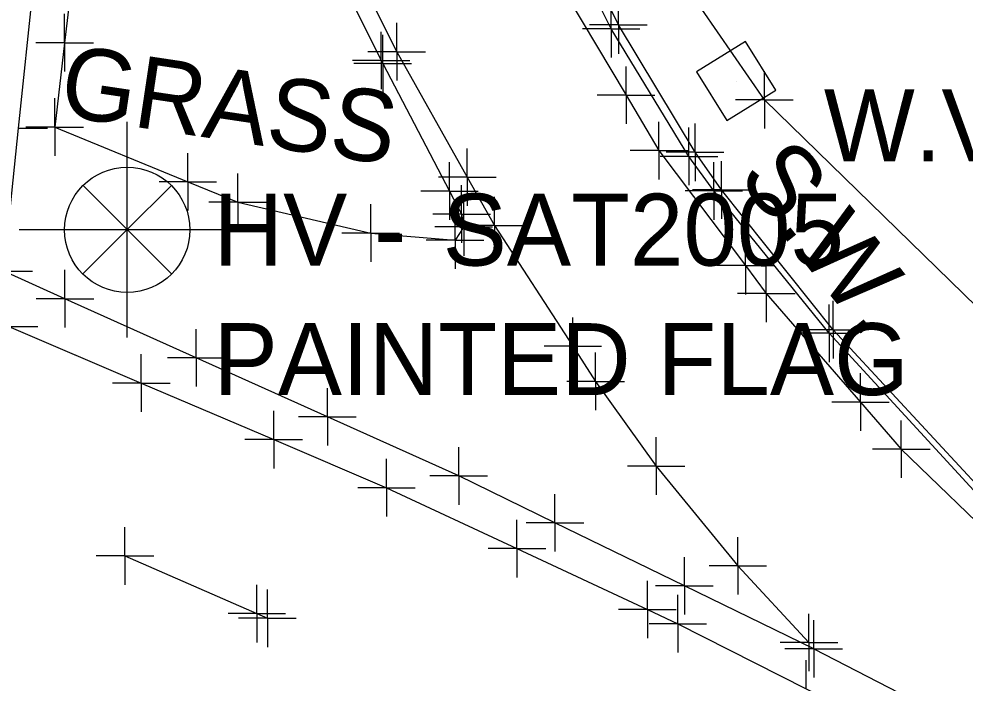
# Model space of a CAD drawing. Extents: x 0 to 1944463, y 0 to 420651.
# Drawn here: x 1942744.5 to 1942810.2, y 417858.9 to 417905.1 of the extents above; entities that cross this region are included whole.
import ezdxf

# ---------------------------------------------------------------- set-up
doc = ezdxf.new("R2010")
doc.units = 0
for name, color, linetype in [('AERIAL - CTRL - Points', 7, 'Continuous'), ('AERIAL - CTRL - Text', 7, 'Continuous'), ('SUR - DTM - Breaklines', 7, 'Continuous'), ('SUR - DTM - Breaklines - Points - Locators', 7, 'Continuous'), ('SUR - TR-CTRL - Pavement Marking', 7, 'Continuous'), ('SUR - TR-CTRL - Pavement Marking - Points - Locators', 7, 'Continuous'), ('SUR - TRAN - Features', 7, 'Continuous'), ('SUR - TRAN - Features - Points - Locators', 7, 'Continuous'), ('SUR - TRAN - Features Text', 7, 'Continuous'), ('SUR - UTL - Water', 7, 'Continuous'), ('SUR - UTL - Water Text', 7, 'Continuous'), ('SUR - VEG - Features Text', 7, 'Continuous')]:
    doc.layers.add(name, color=color, linetype=linetype)

msp = doc.modelspace()

# ---------------------------------------------------------------- linework, layer by layer
at = {"layer": 'AERIAL - CTRL - Points'}
for p, q in [((1942752.036, 417890.416), (1942752.036, 417897.916)), ((1942752.036, 417890.416), (1942748.967, 417893.485)), ((1942752.036, 417890.416), (1942755.104, 417893.485)), ((1942744.536, 417890.416), (1942752.036, 417890.416)), ((1942748.952, 417887.333), (1942752.036, 417890.416)), ((1942752.036, 417890.416), (1942752.036, 417890.416)), ((1942752.036, 417890.416), (1942759.536, 417890.416)), ((1942755.119, 417887.333), (1942752.036, 417890.416)), ((1942752.036, 417882.917), (1942752.036, 417890.416))]:
    msp.add_line(p, q, dxfattribs=at)
msp.add_circle((1942752.036, 417890.401), 4.35, dxfattribs=at)
at = {"layer": 'SUR - DTM - Breaklines'}
msp.add_lwpolyline([(1942845.653, 417851.435), (1942844.565, 417850.194), (1942842.765, 417849.553), (1942840.798, 417849.919), (1942830.793, 417855.545), (1942821.429, 417862.859), (1942815.227, 417868.426), (1942812.749, 417870.855), (1942801.064, 417883.457), (1942793.306, 417893.178), (1942791.482, 417895.793), (1942786.152, 417904.647), (1942777.316, 417922.399), (1942769.183, 417947.203), (1942767.419, 417957.597), (1942765.99, 417970.655), (1942765.855, 417974.495), (1942767.539, 418005.277), (1942768.104, 418011.353)], dxfattribs=at)
at = {"layer": 'SUR - DTM - Breaklines - Points - Locators'}
for p, q in [((1942786.152, 417904.647), (1942786.152, 417906.647)), ((1942786.152, 417904.647), (1942784.152, 417904.647)), ((1942786.152, 417904.647), (1942788.152, 417904.647)), ((1942786.152, 417904.647), (1942786.152, 417902.647)), ((1942791.482, 417895.793), (1942791.482, 417897.793)), ((1942791.482, 417895.793), (1942789.482, 417895.793)), ((1942791.482, 417895.793), (1942793.482, 417895.793)), ((1942791.482, 417895.793), (1942791.482, 417893.793)), ((1942793.306, 417893.178), (1942793.306, 417895.178)), ((1942793.306, 417893.178), (1942791.306, 417893.178)), ((1942793.306, 417893.178), (1942795.306, 417893.178)), ((1942793.306, 417893.178), (1942793.306, 417891.178)), ((1942801.064, 417883.457), (1942801.064, 417885.457)), ((1942801.064, 417883.457), (1942799.064, 417883.457)), ((1942801.064, 417883.457), (1942803.064, 417883.457)), ((1942801.064, 417883.457), (1942801.064, 417881.457))]:
    msp.add_line(p, q, dxfattribs=at)
at = {"layer": 'SUR - TR-CTRL - Pavement Marking'}
for points in [[(1942756.253, 418008.604), (1942756.832, 417999.459), (1942757.925, 417989.519), (1942758.231, 417986.732), (1942760.046, 417976.898), (1942760.467, 417974.617), (1942762.281, 417964.783), (1942762.952, 417961.148), (1942765.097, 417952.301), (1942767.192, 417944.847), (1942770.176, 417935.303), (1942770.256, 417935.048), (1942772.517, 417928.408), (1942775.859, 417919.929), (1942780.296, 417910.968), (1942781.583, 417908.367), (1942786.685, 417899.767), (1942788.971, 417895.911), (1942794.975, 417887.914), (1942796.42, 417885.987), (1942802.968, 417878.429), (1942805.803, 417875.157), (1942813, 417868.214)], [(1942799.725, 417861.277), (1942790.736, 417865.658), (1942781.747, 417870.039), (1942775.062, 417873.297), (1942765.944, 417877.403), (1942756.825, 417881.508), (1942747.707, 417885.614), (1942743.465, 417887.524), (1942744.493, 417897.471), (1942745.521, 417907.418), (1942746.549, 417917.365), (1942747.578, 417927.312), (1942748.606, 417937.259), (1942749.634, 417947.206), (1942750.63, 417956.84)], [(1942752.579, 417949.819), (1942754.255, 417944.892), (1942756.21, 417938.529), (1942758.752, 417930.8), (1942761.496, 417923.192), (1942763.64, 417917.67), (1942766.697, 417910.933), (1942770.76, 417902.785), (1942775.654, 417894.064), (1942777.544, 417890.697), (1942782.986, 417882.308), (1942784.568, 417879.87), (1942788.778, 417873.987), (1942794.451, 417867.048), (1942799.385, 417861.72)], [(1942743.821, 417883.68), (1942753.017, 417879.751), (1942762.213, 417875.823), (1942770.046, 417872.476), (1942779.106, 417868.245), (1942788.166, 417864.013), (1942790.281, 417863.025), (1942799.195, 417858.492), (1942808.108, 417853.959), (1942814.469, 417850.724), (1942823.271, 417845.977), (1942832.073, 417841.23), (1942837.137, 417838.5), (1942845.787, 417833.481), (1942854.436, 417828.462), (1942863.086, 417823.444), (1942865.149, 417822.246), (1942873.606, 417816.91), (1942882.063, 417811.573), (1942888.586, 417807.457), (1942896.946, 417801.969)], [(1942751.882, 417867.738), (1942761.042, 417863.726), (1942761.775, 417863.405)]]:
    msp.add_lwpolyline(points, dxfattribs=at)
at = {"layer": 'SUR - TR-CTRL - Pavement Marking - Points - Locators'}
for p, q in [((1942770.76, 417902.785), (1942770.76, 417904.785)), ((1942770.76, 417902.785), (1942768.76, 417902.785)), ((1942770.76, 417902.785), (1942772.76, 417902.785)), ((1942770.76, 417902.785), (1942770.76, 417900.785)), ((1942786.685, 417899.767), (1942786.685, 417901.767)), ((1942786.685, 417899.767), (1942784.685, 417899.767)), ((1942786.685, 417899.767), (1942788.685, 417899.767)), ((1942786.685, 417899.767), (1942786.685, 417897.767)), ((1942744.493, 417897.471), (1942746.493, 417897.471)), ((1942788.971, 417895.911), (1942788.971, 417897.911)), ((1942775.654, 417894.064), (1942775.654, 417896.064)), ((1942788.971, 417895.911), (1942786.971, 417895.911)), ((1942788.971, 417895.911), (1942790.971, 417895.911)), ((1942788.971, 417895.911), (1942788.971, 417893.911)), ((1942775.654, 417894.064), (1942773.654, 417894.064)), ((1942775.654, 417894.064), (1942777.654, 417894.064)), ((1942775.654, 417894.064), (1942775.654, 417892.064)), ((1942777.544, 417890.697), (1942777.544, 417892.697)), ((1942777.544, 417890.697), (1942775.544, 417890.697)), ((1942777.544, 417890.697), (1942779.544, 417890.697)), ((1942777.544, 417890.697), (1942777.544, 417888.697)), ((1942794.975, 417887.914), (1942794.975, 417889.914)), ((1942743.465, 417887.524), (1942745.465, 417887.524)), ((1942747.707, 417885.614), (1942747.707, 417887.614)), ((1942794.975, 417887.914), (1942792.975, 417887.914)), ((1942794.975, 417887.914), (1942796.975, 417887.914)), ((1942794.975, 417887.914), (1942794.975, 417885.914)), ((1942796.42, 417885.987), (1942796.42, 417887.987)), ((1942747.707, 417885.614), (1942745.707, 417885.614)), ((1942747.707, 417885.614), (1942749.707, 417885.614)), ((1942747.707, 417885.614), (1942747.707, 417883.614)), ((1942796.42, 417885.987), (1942794.42, 417885.987)), ((1942796.42, 417885.987), (1942798.42, 417885.987)), ((1942796.42, 417885.987), (1942796.42, 417883.987)), ((1942782.986, 417882.308), (1942782.986, 417884.308)), ((1942743.821, 417883.68), (1942745.821, 417883.68)), ((1942756.825, 417881.508), (1942756.825, 417883.508)), ((1942782.986, 417882.308), (1942780.986, 417882.308)), ((1942782.986, 417882.308), (1942784.986, 417882.308)), ((1942782.986, 417882.308), (1942782.986, 417880.308)), ((1942753.017, 417879.751), (1942753.017, 417881.751)), ((1942784.568, 417879.87), (1942784.568, 417881.87)), ((1942756.825, 417881.508), (1942754.825, 417881.508)), ((1942756.825, 417881.508), (1942758.825, 417881.508)), ((1942756.825, 417881.508), (1942756.825, 417879.508)), ((1942802.968, 417878.429), (1942802.968, 417880.429)), ((1942753.017, 417879.751), (1942751.017, 417879.751)), ((1942753.017, 417879.751), (1942755.017, 417879.751)), ((1942753.017, 417879.751), (1942753.017, 417877.751)), ((1942784.568, 417879.87), (1942782.568, 417879.87)), ((1942784.568, 417879.87), (1942786.568, 417879.87)), ((1942784.568, 417879.87), (1942784.568, 417877.87)), ((1942765.944, 417877.403), (1942765.944, 417879.403)), ((1942802.968, 417878.429), (1942800.968, 417878.429)), ((1942802.968, 417878.429), (1942804.968, 417878.429)), ((1942802.968, 417878.429), (1942802.968, 417876.429)), ((1942762.213, 417875.823), (1942762.213, 417877.823)), ((1942765.944, 417877.403), (1942763.944, 417877.403)), ((1942765.944, 417877.403), (1942767.944, 417877.403)), ((1942765.944, 417877.403), (1942765.944, 417875.403)), ((1942805.803, 417875.157), (1942805.803, 417877.157)), ((1942762.213, 417875.823), (1942760.213, 417875.823)), ((1942762.213, 417875.823), (1942764.213, 417875.823)), ((1942762.213, 417875.823), (1942762.213, 417873.823)), ((1942788.778, 417873.987), (1942788.778, 417875.987)), ((1942775.062, 417873.297), (1942775.062, 417875.297)), ((1942805.803, 417875.157), (1942803.803, 417875.157)), ((1942805.803, 417875.157), (1942807.803, 417875.157)), ((1942805.803, 417875.157), (1942805.803, 417873.157)), ((1942770.046, 417872.476), (1942770.046, 417874.476)), ((1942788.778, 417873.987), (1942786.778, 417873.987)), ((1942788.778, 417873.987), (1942790.778, 417873.987)), ((1942788.778, 417873.987), (1942788.778, 417871.987)), ((1942775.062, 417873.297), (1942773.062, 417873.297)), ((1942775.062, 417873.297), (1942777.062, 417873.297)), ((1942775.062, 417873.297), (1942775.062, 417871.297)), ((1942770.046, 417872.476), (1942768.046, 417872.476)), ((1942770.046, 417872.476), (1942772.046, 417872.476)), ((1942770.046, 417872.476), (1942770.046, 417870.476)), ((1942781.747, 417870.039), (1942781.747, 417872.039)), ((1942779.106, 417868.245), (1942779.106, 417870.245)), ((1942781.747, 417870.039), (1942779.747, 417870.039)), ((1942781.747, 417870.039), (1942783.747, 417870.039)), ((1942781.747, 417870.039), (1942781.747, 417868.039)), ((1942751.882, 417867.738), (1942751.882, 417869.738)), ((1942794.451, 417867.048), (1942794.451, 417869.048)), ((1942779.106, 417868.245), (1942777.106, 417868.245)), ((1942779.106, 417868.245), (1942781.106, 417868.245)), ((1942779.106, 417868.245), (1942779.106, 417866.245)), ((1942751.882, 417867.738), (1942749.882, 417867.738)), ((1942751.882, 417867.738), (1942753.882, 417867.738)), ((1942751.882, 417867.738), (1942751.882, 417865.738)), ((1942790.736, 417865.658), (1942790.736, 417867.658)), ((1942794.451, 417867.048), (1942792.451, 417867.048)), ((1942794.451, 417867.048), (1942796.451, 417867.048)), ((1942794.451, 417867.048), (1942794.451, 417865.048)), ((1942788.166, 417864.013), (1942788.166, 417866.013)), ((1942761.042, 417863.726), (1942761.042, 417865.726)), ((1942761.775, 417863.405), (1942761.775, 417865.405)), ((1942790.736, 417865.658), (1942788.736, 417865.658)), ((1942790.736, 417865.658), (1942792.736, 417865.658)), ((1942790.736, 417865.658), (1942790.736, 417863.658)), ((1942790.281, 417863.025), (1942790.281, 417865.025)), ((1942788.166, 417864.013), (1942786.166, 417864.013)), ((1942788.166, 417864.013), (1942790.166, 417864.013)), ((1942788.166, 417864.013), (1942788.166, 417862.013)), ((1942761.042, 417863.726), (1942759.042, 417863.726)), ((1942761.775, 417863.405), (1942759.775, 417863.405)), ((1942761.042, 417863.726), (1942763.042, 417863.726)), ((1942761.042, 417863.726), (1942761.042, 417861.726)), ((1942761.775, 417863.405), (1942763.775, 417863.405)), ((1942761.775, 417863.405), (1942761.775, 417861.405)), ((1942799.385, 417861.72), (1942799.385, 417863.72)), ((1942799.725, 417861.277), (1942799.725, 417863.277)), ((1942790.281, 417863.025), (1942788.281, 417863.025)), ((1942790.281, 417863.025), (1942792.281, 417863.025)), ((1942790.281, 417863.025), (1942790.281, 417861.025)), ((1942799.385, 417861.72), (1942797.385, 417861.72)), ((1942799.725, 417861.277), (1942797.725, 417861.277)), ((1942799.385, 417861.72), (1942801.385, 417861.72)), ((1942799.385, 417861.72), (1942799.385, 417859.72)), ((1942799.725, 417861.277), (1942801.725, 417861.277)), ((1942799.725, 417861.277), (1942799.725, 417859.277)), ((1942799.195, 417858.492), (1942799.195, 417860.492))]:
    msp.add_line(p, q, dxfattribs=at)
at = {"layer": 'SUR - TRAN - Features'}
for q in [(1942799.725, 417863.277), (1942797.725, 417861.277), (1942801.725, 417861.277), (1942799.725, 417859.277)]:
    msp.add_line((1942799.725, 417861.277), q, dxfattribs=at)
for points in [[(1942846.028, 417851.164), (1942844.827, 417849.664), (1942842.876, 417848.99), (1942840.571, 417849.513), (1942830.462, 417855.144), (1942821.094, 417862.458), (1942814.609, 417868.3), (1942812.416, 417870.575), (1942800.802, 417883.21), (1942792.78, 417893.105), (1942791.056, 417895.511), (1942785.649, 417904.372), (1942776.765, 417922.192), (1942768.712, 417946.981), (1942766.861, 417957.603), (1942765.443, 417970.756), (1942765.289, 417974.421), (1942766.953, 418005.16), (1942767.653, 418011.44)], [(1943114.834, 417624.896), (1943103.453, 417639.126), (1943095.3, 417651.485), (1943083.428, 417672.654), (1943076.721, 417682.249), (1943055.252, 417704.387), (1943020.966, 417735.536), (1942996.784, 417756.051), (1942978.451, 417770.697), (1942923.479, 417810.417), (1942907.463, 417821.141), (1942884.283, 417835.758), (1942865.83, 417846.651), (1942848.31, 417856.509), (1942835.5, 417863.859), (1942826.295, 417870.821), (1942818.403, 417877.862), (1942796.294, 417899.443), (1942790.861, 417907.343), (1942782.321, 417924.544), (1942774.775, 417947.78), (1942772.79, 417958.555), (1942771.547, 417970.782), (1942773.585, 418011.209)], [(1942753.999, 417939.444), (1942753.169, 417939.851), (1942752.765, 417939.496), (1942751.654, 417936.999), (1942750.904, 417930.641), (1942749.732, 417920.71), (1942748.862, 417913.338), (1942747.69, 417903.406), (1942746.999, 417897.544), (1942756.247, 417893.74), (1942759.709, 417892.316), (1942768.947, 417890.177), (1942774.807, 417889.694)], [(1942753.999, 417939.444), (1942757.564, 417930.274), (1942761.188, 417920.953), (1942762.601, 417917.318), (1942765.22, 417911.131), (1942769.673, 417902.177), (1942769.783, 417901.956), (1942774.424, 417893.098), (1942775.263, 417891.498), (1942775.407, 417890.601), (1942774.807, 417889.694)], [(1942799.725, 417861.277), (1942808.615, 417856.696), (1942815.567, 417853.113), (1942824.359, 417848.347), (1942833.15, 417843.582), (1942833.405, 417843.443), (1942842.112, 417838.524), (1942850.818, 417833.605), (1942856.096, 417830.623), (1942864.658, 417825.457), (1942873.22, 417820.29), (1942877.962, 417817.43), (1942886.414, 417812.085), (1942894.204, 417807.16)]]:
    msp.add_lwpolyline(points, dxfattribs=at)
at = {"layer": 'SUR - TRAN - Features - Points - Locators'}
for p, q in [((1942785.649, 417904.372), (1942785.649, 417906.372)), ((1942747.69, 417903.406), (1942747.69, 417905.406)), ((1942769.673, 417902.177), (1942769.673, 417904.177)), ((1942769.783, 417901.956), (1942769.783, 417903.956)), ((1942785.649, 417904.372), (1942783.649, 417904.372)), ((1942785.649, 417904.372), (1942787.649, 417904.372)), ((1942785.649, 417904.372), (1942785.649, 417902.372)), ((1942747.69, 417903.406), (1942745.69, 417903.406)), ((1942747.69, 417903.406), (1942749.69, 417903.406)), ((1942747.69, 417903.406), (1942747.69, 417901.406)), ((1942769.673, 417902.177), (1942767.673, 417902.177)), ((1942769.783, 417901.956), (1942767.783, 417901.956)), ((1942769.673, 417902.177), (1942771.673, 417902.177)), ((1942769.673, 417902.177), (1942769.673, 417900.177)), ((1942769.783, 417901.956), (1942771.783, 417901.956)), ((1942769.783, 417901.956), (1942769.783, 417899.956)), ((1942796.294, 417899.443), (1942796.294, 417901.443)), ((1942746.999, 417897.544), (1942746.999, 417899.544)), ((1942796.294, 417899.443), (1942794.294, 417899.443)), ((1942796.294, 417899.443), (1942798.294, 417899.443)), ((1942796.294, 417899.443), (1942796.294, 417897.443)), ((1942746.999, 417897.544), (1942744.999, 417897.544)), ((1942746.999, 417897.544), (1942748.999, 417897.544)), ((1942746.999, 417897.544), (1942746.999, 417895.544)), ((1942791.056, 417895.511), (1942791.056, 417897.511)), ((1942756.247, 417893.74), (1942756.247, 417895.74)), ((1942791.056, 417895.511), (1942789.056, 417895.511)), ((1942791.056, 417895.511), (1942793.056, 417895.511)), ((1942791.056, 417895.511), (1942791.056, 417893.511)), ((1942774.424, 417893.098), (1942774.424, 417895.098)), ((1942792.78, 417893.105), (1942792.78, 417895.105)), ((1942759.709, 417892.316), (1942759.709, 417894.316)), ((1942756.247, 417893.74), (1942754.247, 417893.74)), ((1942756.247, 417893.74), (1942758.247, 417893.74)), ((1942756.247, 417893.74), (1942756.247, 417891.74)), ((1942775.263, 417891.498), (1942775.263, 417893.498)), ((1942774.424, 417893.098), (1942772.424, 417893.098)), ((1942774.424, 417893.098), (1942776.424, 417893.098)), ((1942774.424, 417893.098), (1942774.424, 417891.098)), ((1942792.78, 417893.105), (1942790.78, 417893.105)), ((1942792.78, 417893.105), (1942794.78, 417893.105)), ((1942792.78, 417893.105), (1942792.78, 417891.105)), ((1942759.709, 417892.316), (1942757.709, 417892.316)), ((1942759.709, 417892.316), (1942761.709, 417892.316)), ((1942759.709, 417892.316), (1942759.709, 417890.316)), ((1942768.947, 417890.177), (1942768.947, 417892.177)), ((1942775.407, 417890.601), (1942775.407, 417892.601)), ((1942775.263, 417891.498), (1942773.263, 417891.498)), ((1942774.807, 417889.694), (1942774.807, 417891.694)), ((1942774.807, 417889.694), (1942774.807, 417891.694)), ((1942775.263, 417891.498), (1942777.263, 417891.498)), ((1942775.263, 417891.498), (1942775.263, 417889.498)), ((1942768.947, 417890.177), (1942766.947, 417890.177)), ((1942768.947, 417890.177), (1942770.947, 417890.177)), ((1942768.947, 417890.177), (1942768.947, 417888.177)), ((1942775.407, 417890.601), (1942773.407, 417890.601)), ((1942775.407, 417890.601), (1942777.407, 417890.601)), ((1942775.407, 417890.601), (1942775.407, 417888.601)), ((1942774.807, 417889.694), (1942772.807, 417889.694)), ((1942774.807, 417889.694), (1942772.807, 417889.694)), ((1942774.807, 417889.694), (1942776.807, 417889.694)), ((1942774.807, 417889.694), (1942774.807, 417887.694)), ((1942774.807, 417889.694), (1942776.807, 417889.694)), ((1942774.807, 417889.694), (1942774.807, 417887.694)), ((1942800.802, 417883.21), (1942800.802, 417885.21)), ((1942800.802, 417883.21), (1942798.802, 417883.21)), ((1942800.802, 417883.21), (1942802.802, 417883.21)), ((1942800.802, 417883.21), (1942800.802, 417881.21))]:
    msp.add_line(p, q, dxfattribs=at)
at = {"layer": 'SUR - UTL - Water'}
msp.add_line((1942794.331, 417900.745), (1942794.331, 417900.745), dxfattribs=at)
msp.add_lwpolyline([(1942794.972, 417903.5), (1942791.576, 417901.386), (1942793.69, 417897.991), (1942797.086, 417900.104), (1942794.972, 417903.5)], dxfattribs=at)

# ---------------------------------------------------------------- texts
at = {"layer": 'AERIAL - CTRL - Text'}
for s, height, p in [('HV - ', 5, (1942758.036, 417887.916)), ('SAT2005', 5, (1942773.947, 417887.916)), ('PAINTED FLAG', 4.99999, (1942758.036, 417878.916))]:
    msp.add_text(s, height=height, dxfattribs=at).set_placement(p)
at = {"layer": 'SUR - TRAN - Features Text'}
msp.add_text('S.W.', height=5, rotation=308.51663, dxfattribs=at).set_placement((1942794.336, 417894.048))
at = {"layer": 'SUR - UTL - Water Text'}
msp.add_text('W.V.', height=5, dxfattribs=at).set_placement((1942800.428, 417895.158))
at = {"layer": 'SUR - VEG - Features Text'}
msp.add_text('GRASS', height=5, rotation=351.48625, dxfattribs=at).set_placement((1942747.19, 417898.364))

doc.saveas('drawing.dxf')
